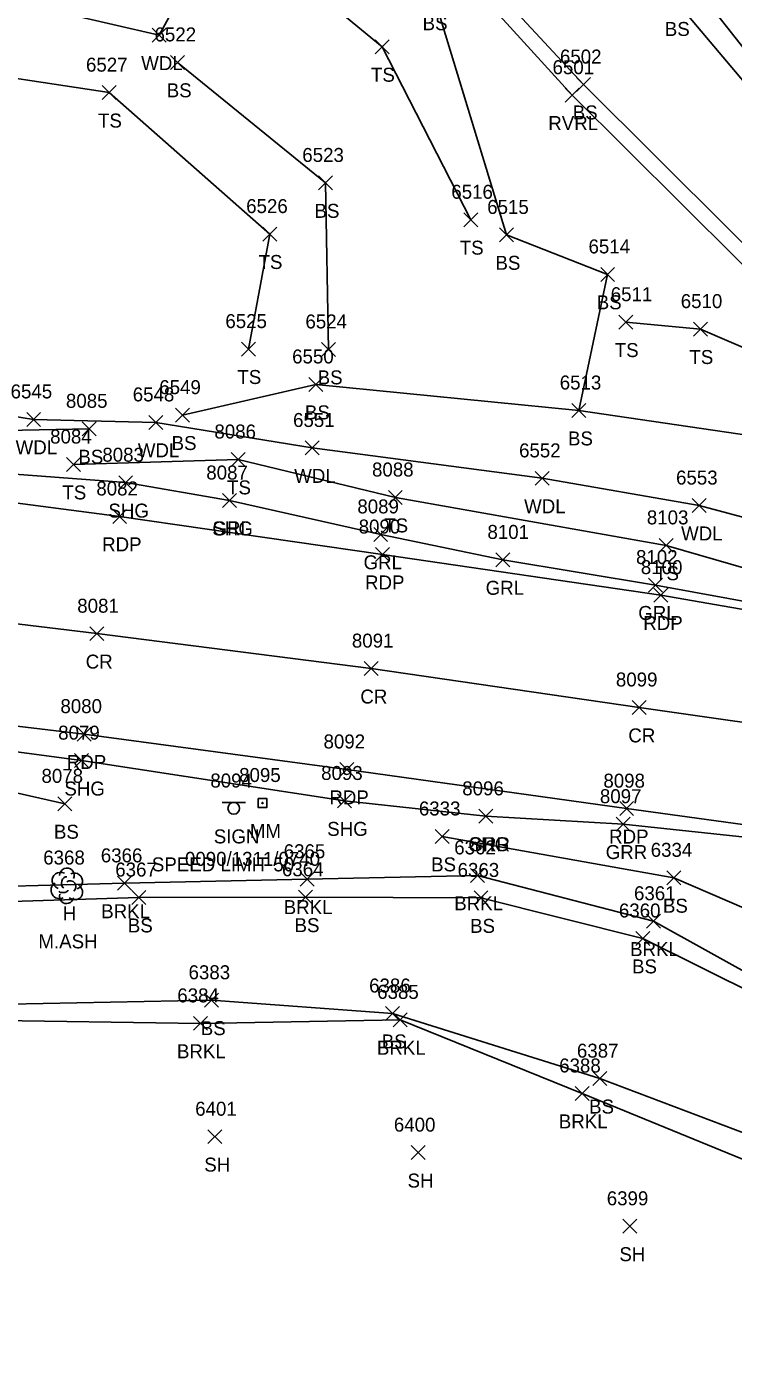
# Model space of a CAD drawing. Extents: x 1588028 to 1589597, y 137576 to 138176.
# Drawn here: x 1588774.4 to 1588875.5, y 137778.7 to 137969.2 of the extents above; entities that cross this region are included whole.
import ezdxf

# ---------------------------------------------------------------- set-up
doc = ezdxf.new("R2010")
doc.units = 0
for name, color, linetype in [('L_A', 7, 'Continuous'), ('L_C', 7, 'Continuous'), ('L_I', 7, 'Continuous'), ('L_TIC', 7, 'Continuous'), ('LAWA', 7, 'Continuous'), ('LAWE', 7, 'Continuous'), ('LELB', 7, 'Continuous'), ('LTD', 7, 'Continuous'), ('P_A', 7, 'Continuous'), ('P_I', 7, 'Continuous'), ('P_TIC', 7, 'Continuous'), ('PET', 7, 'Continuous'), ('PRC', 7, 'Continuous'), ('PSU', 7, 'Continuous'), ('R_A', 7, 'Continuous'), ('R_I', 7, 'Continuous'), ('R_TIC', 7, 'Continuous'), ('RGR', 7, 'Continuous'), ('S_A', 7, 'Continuous'), ('S_C', 7, 'Continuous'), ('S_I', 7, 'Continuous'), ('SRM', 7, 'Continuous'), ('SSGN', 7, 'Continuous')]:
    doc.layers.add(name, color=color, linetype=linetype)

msp = doc.modelspace()

# ---------------------------------------------------------------- linework, layer by layer
at = {"layer": 'L_TIC'}
for points in [[(1588792.35, 137966.95), (1588794.35, 137968.95)], [(1588794.35, 137966.95), (1588792.35, 137968.95)], [(1588824.25, 137965.29), (1588826.25, 137967.29)], [(1588826.25, 137965.29), (1588824.25, 137967.29)], [(1588794.99, 137963.06), (1588796.99, 137965.06)], [(1588796.99, 137963.06), (1588794.99, 137965.06)], [(1588853.1, 137959.89), (1588855.1, 137961.89)], [(1588855.1, 137959.89), (1588853.1, 137961.89)], [(1588785.18, 137958.73), (1588787.18, 137960.73)], [(1588787.18, 137958.73), (1588785.18, 137960.73)], [(1588851.47, 137958.37), (1588853.47, 137960.37)], [(1588853.47, 137958.37), (1588851.47, 137960.37)], [(1588816.14, 137945.81), (1588818.14, 137947.81)], [(1588818.14, 137945.81), (1588816.14, 137947.81)], [(1588836.96, 137940.54), (1588838.96, 137942.54)], [(1588838.96, 137940.54), (1588836.96, 137942.54)], [(1588808.17, 137938.49), (1588810.17, 137940.49)], [(1588810.17, 137938.49), (1588808.17, 137940.49)], [(1588842.04, 137938.37), (1588844.04, 137940.37)], [(1588844.04, 137938.37), (1588842.04, 137940.37)], [(1588856.54, 137932.72), (1588858.54, 137934.72)], [(1588858.54, 137932.72), (1588856.54, 137934.72)], [(1588859.16, 137925.88), (1588861.16, 137927.88)], [(1588861.16, 137925.88), (1588859.16, 137927.88)], [(1588869.83, 137924.89), (1588871.83, 137926.89)], [(1588871.83, 137924.89), (1588869.83, 137926.89)], [(1588805.13, 137922.03), (1588807.13, 137924.03)], [(1588807.13, 137922.03), (1588805.13, 137924.03)], [(1588816.59, 137921.98), (1588818.59, 137923.98)], [(1588818.59, 137921.98), (1588816.59, 137923.98)], [(1588814.77, 137916.97), (1588816.77, 137918.97)], [(1588816.77, 137916.97), (1588814.77, 137918.97)], [(1588852.42, 137913.24), (1588854.42, 137915.24)], [(1588854.42, 137913.24), (1588852.42, 137915.24)], [(1588774.38, 137911.97), (1588776.38, 137913.97)], [(1588776.38, 137911.97), (1588774.38, 137913.97)], [(1588791.87, 137911.54), (1588793.87, 137913.54)], [(1588793.87, 137911.54), (1588791.87, 137913.54)], [(1588795.68, 137912.58), (1588797.68, 137914.58)], [(1588797.68, 137912.58), (1588795.68, 137914.58)], [(1588782.34, 137910.62), (1588784.34, 137912.62)], [(1588784.34, 137910.62), (1588782.34, 137912.62)], [(1588814.25, 137907.88), (1588816.25, 137909.88)], [(1588816.25, 137907.88), (1588814.25, 137909.88)], [(1588780.08, 137905.51), (1588782.08, 137907.51)], [(1588782.08, 137905.51), (1588780.08, 137907.51)], [(1588803.65, 137906.23), (1588805.65, 137908.23)], [(1588805.65, 137906.23), (1588803.65, 137908.23)], [(1588847.17, 137903.53), (1588849.17, 137905.53)], [(1588849.17, 137903.53), (1588847.17, 137905.53)], [(1588826.15, 137900.79), (1588828.15, 137902.79)], [(1588828.15, 137900.79), (1588826.15, 137902.79)], [(1588869.64, 137899.64), (1588871.64, 137901.64)], [(1588871.64, 137899.64), (1588869.64, 137901.64)], [(1588864.92, 137893.94), (1588866.92, 137895.94)], [(1588866.92, 137893.94), (1588864.92, 137895.94)], [(1588778.84, 137856.95), (1588780.84, 137858.95)], [(1588780.84, 137856.95), (1588778.84, 137858.95)], [(1588832.83, 137852.28), (1588834.83, 137854.28)], [(1588834.83, 137852.28), (1588832.83, 137854.28)], [(1588837.93, 137846.71), (1588839.93, 137848.71)], [(1588839.93, 137846.71), (1588837.93, 137848.71)], [(1588787.4, 137845.57), (1588789.4, 137847.57)], [(1588789.4, 137845.57), (1588787.4, 137847.57)], [(1588813.53, 137846.16), (1588815.53, 137848.16)], [(1588815.53, 137846.16), (1588813.53, 137848.16)], [(1588866.01, 137846.36), (1588868.01, 137848.36)], [(1588868.01, 137846.36), (1588866.01, 137848.36)], [(1588789.42, 137843.54), (1588791.42, 137845.54)], [(1588791.42, 137843.54), (1588789.42, 137845.54)], [(1588813.28, 137843.58), (1588815.28, 137845.58)], [(1588815.28, 137843.58), (1588813.28, 137845.58)], [(1588838.41, 137843.48), (1588840.41, 137845.48)], [(1588840.41, 137843.48), (1588838.41, 137845.48)], [(1588863.1, 137840.15), (1588865.1, 137842.15)], [(1588865.1, 137840.15), (1588863.1, 137842.15)], [(1588861.59, 137837.68), (1588863.59, 137839.68)], [(1588863.59, 137837.68), (1588861.59, 137839.68)], [(1588799.85, 137828.84), (1588801.85, 137830.84)], [(1588801.85, 137828.84), (1588799.85, 137830.84)], [(1588798.24, 137825.53), (1588800.24, 137827.53)], [(1588800.24, 137825.53), (1588798.24, 137827.53)], [(1588825.76, 137826.94), (1588827.76, 137828.94)], [(1588827.76, 137826.94), (1588825.76, 137828.94)], [(1588826.86, 137826.03), (1588828.86, 137828.03)], [(1588828.86, 137826.03), (1588826.86, 137828.03)], [(1588855.44, 137817.62), (1588857.44, 137819.62)], [(1588857.44, 137817.62), (1588855.44, 137819.62)], [(1588852.9, 137815.5), (1588854.9, 137817.5)], [(1588854.9, 137815.5), (1588852.9, 137817.5)], [(1588800.32, 137809.31), (1588802.32, 137811.31)], [(1588802.32, 137809.31), (1588800.32, 137811.31)], [(1588829.41, 137807.03), (1588831.41, 137809.03)], [(1588831.41, 137807.03), (1588829.41, 137809.03)], [(1588859.73, 137796.49), (1588861.73, 137798.49)], [(1588861.73, 137796.49), (1588859.73, 137798.49)]]:
    msp.add_lwpolyline(points, dxfattribs=at)
at = {"layer": 'LAWA'}
for points in [[(1588762.05, 138028.09), (1588788.28, 138004.54), (1588803.93, 137987.32), (1588793.35, 137967.95), (1588766.76, 137974.1)], [(1588745.3, 137917.8), (1588775.38, 137912.97), (1588792.87, 137912.54), (1588815.25, 137908.88), (1588848.17, 137904.53), (1588870.64, 137900.64), (1588891.17, 137895.16)]]:
    msp.add_lwpolyline(points, dxfattribs=at)
at = {"layer": 'LAWE'}
for points in [[(1588434.56, 138062.89), (1588458.47, 138076.79), (1588495.54, 138110.89), (1588517.72, 138151.17), (1588540.38, 138168.38), (1588562.32, 138170.6), (1588586.16, 138148.71), (1588635.49, 138130.01), (1588676.05, 138127.99), (1588706.09, 138118.66), (1588727.82, 138096.85), (1588770.39, 138065.1), (1588798.8, 138043.18), (1588827.56, 138018.04), (1588869.93, 137975.12), (1588899.99, 137936.94), (1588912.08, 137921.5), (1588926.82, 137898.29), (1588932.86, 137884.09), (1588938.83, 137878.76)], [(1588441.02, 138044.54), (1588465.05, 138060.11), (1588492.43, 138083.39), (1588521.86, 138113.88), (1588530.72, 138143.54), (1588545.57, 138151.23), (1588554.85, 138142.99), (1588577.1, 138115.96), (1588614.25, 138110.98), (1588643.88, 138111.05), (1588664.41, 138106.89), (1588688.53, 138102.18), (1588718.75, 138082.48), (1588743.28, 138056.23), (1588764.53, 138038.44), (1588797.04, 138013.98), (1588814.47, 138001.04), (1588852.47, 137959.37), (1588883.95, 137928.09), (1588897.47, 137912.79), (1588913.44, 137894.45), (1588920.69, 137884.16), (1588921.99, 137878.45)], [(1588977.09, 137801.88), (1588949.99, 137800.55), (1588913.53, 137816.71), (1588888.44, 137827.65), (1588864.1, 137841.15), (1588838.93, 137847.71), (1588814.53, 137847.16), (1588788.4, 137846.57), (1588760.06, 137845.85), (1588744.31, 137852.31), (1588711.69, 137843.68)], [(1588713.41, 137823.71), (1588738.42, 137825.5), (1588767.27, 137826.98), (1588799.24, 137826.53), (1588827.86, 137827.03), (1588853.9, 137816.5), (1588892.67, 137800.6), (1588920.93, 137790.22), (1588953.81, 137785.34), (1588994.96, 137778.72)]]:
    msp.add_lwpolyline(points, dxfattribs=at)
at = {"layer": 'LELB'}
for points in [[(1588682.05, 138125.09), (1588705.48, 138117.82), (1588727.76, 138095.08), (1588769.43, 138063.36), (1588798.46, 138041.61), (1588826.19, 138016.5), (1588867.28, 137972.84), (1588898.61, 137935.76), (1588911.42, 137921.16), (1588925.66, 137898.09), (1588931.8, 137883.5), (1588937.54, 137876.95)], [(1588667.09, 138110.74), (1588688.84, 138110.6), (1588719.17, 138088.33), (1588744.4, 138063.38), (1588766.27, 138045.61), (1588798.27, 138018.43), (1588815.99, 138001.93), (1588854.1, 137960.89), (1588885.58, 137929.53), (1588899.45, 137912.94)], [(1588879.77, 137910.36), (1588853.42, 137914.24), (1588857.54, 137933.72), (1588843.04, 137939.37), (1588832.61, 137973.66), (1588809.98, 137996.61)], [(1588837.96, 137941.54), (1588825.25, 137966.29), (1588808.87, 137979.84)], [(1588806.13, 137923.03), (1588809.17, 137939.49), (1588786.18, 137959.73), (1588761.56, 137963.45), (1588758.19, 137959.11), (1588739.31, 137921.58)], [(1588795.99, 137964.06), (1588817.14, 137946.81), (1588817.59, 137922.98)], [(1588551.14, 137930.49), (1588555.16, 137922.7), (1588594.96, 137920.46), (1588624.61, 137918.77), (1588663.54, 137916.63), (1588704.8, 137915.23), (1588747.54, 137910.9), (1588783.34, 137911.62)], [(1588898.43, 137890.84), (1588893.87, 137897.04), (1588887.93, 137918.51), (1588870.83, 137925.89), (1588860.16, 137926.88)], [(1588796.68, 137913.58), (1588815.77, 137917.97)], [(1588815.77, 137917.97), (1588853.42, 137914.24)], [(1588781.08, 137906.51), (1588804.65, 137907.23), (1588827.15, 137901.79), (1588865.92, 137894.94), (1588900.81, 137884.83), (1588902.22, 137883.09)], [(1588723.44, 137868.13), (1588739.55, 137867.04), (1588779.84, 137857.95)], [(1588833.83, 137853.28), (1588867.01, 137847.36), (1588885.07, 137839.59), (1588900.79, 137841.16), (1588903.14, 137846.71), (1588926.9, 137843.7)], [(1588976.95, 137800.76), (1588950.62, 137796.9), (1588914.44, 137812.1), (1588887.83, 137826.14), (1588862.59, 137838.68), (1588839.41, 137844.48), (1588814.28, 137844.58), (1588790.42, 137844.54), (1588761.5, 137843.62), (1588744.06, 137845.91), (1588711.1, 137839.15), (1588710.72, 137829.12), (1588738.02, 137826.67), (1588767.07, 137829.2), (1588800.85, 137829.84), (1588826.76, 137827.94), (1588856.44, 137818.62), (1588893.47, 137804.61), (1588923.15, 137792.66), (1588953.98, 137786.08), (1588988.16, 137786.33)]]:
    msp.add_lwpolyline(points, dxfattribs=at)
at = {"layer": 'LTD'}
msp.add_line((1588780.11, 137846.26), (1588780.11, 137846.26), dxfattribs=at)
msp.add_line((1588780.11, 137846.26), (1588780.11, 137846.26), dxfattribs=at)
msp.add_arc((1588780.15, 137847.7), 1.05, 335.5272, 180.9563, dxfattribs=at)
for centre, major_axis, ratio, start_param, end_param in [((1588779.02, 137845.55), (0.58, -1.04), 0.959034, 3.141593, 6.283185), ((1588779.32, 137846.93), (1.21, -0.51), 0.895232, 1.570796, 4.712389), ((1588779.9, 137846.72), (-0.208, -0.792), 0.645439, 3.141593, 6.283185), ((1588780.61, 137846.1), (-0.5, 0.667), 0.989748, 3.141593, 6.283185), ((1588781.15, 137846.85), (-1.14, -0.48), 0.949671, 1.570796, 4.712389), ((1588780.11, 137844.76), (0.26, 1.06), 0.942809, 1.570796, 4.712389), ((1588779.65, 137845.51), (-0.625, -0.083), 0.423636, 0, 3.141593), ((1588781.11, 137845.43), (-1.09, 0.79), 0.841452, 1.570796, 4.712389)]:
    msp.add_ellipse(centre, major_axis=major_axis, ratio=ratio, start_param=start_param, end_param=end_param, dxfattribs=at)
at = {"layer": 'P_TIC'}
for points in [[(1588787.55, 137902.91), (1588789.55, 137904.91)], [(1588789.55, 137902.91), (1588787.55, 137904.91)], [(1588802.43, 137900.36), (1588804.43, 137902.36)], [(1588804.43, 137900.36), (1588802.43, 137902.36)], [(1588786.69, 137898.08), (1588788.69, 137900.08)], [(1588788.69, 137898.08), (1588786.69, 137900.08)], [(1588824.32, 137892.63), (1588826.32, 137894.63)], [(1588826.32, 137892.63), (1588824.32, 137894.63)], [(1588864.15, 137886.82), (1588866.15, 137888.82)], [(1588866.15, 137886.82), (1588864.15, 137888.82)], [(1588783.4, 137881.3), (1588785.4, 137883.3)], [(1588785.4, 137881.3), (1588783.4, 137883.3)], [(1588822.71, 137876.3), (1588824.71, 137878.3)], [(1588824.71, 137876.3), (1588822.71, 137878.3)], [(1588861.06, 137870.74), (1588863.06, 137872.74)], [(1588863.06, 137870.74), (1588861.06, 137872.74)], [(1588781.63, 137866.93), (1588783.63, 137868.93)], [(1588783.63, 137866.93), (1588781.63, 137868.93)], [(1588781.24, 137863.13), (1588783.24, 137865.13)], [(1588783.24, 137863.13), (1588781.24, 137865.13)], [(1588819.21, 137861.87), (1588821.21, 137863.87)], [(1588821.21, 137861.87), (1588819.21, 137863.87)], [(1588818.87, 137857.36), (1588820.87, 137859.36)], [(1588820.87, 137857.36), (1588818.87, 137859.36)], [(1588859.26, 137856.26), (1588861.26, 137858.26)], [(1588861.26, 137856.26), (1588859.26, 137858.26)], [(1588839.12, 137855.16), (1588841.12, 137857.16)], [(1588841.12, 137855.16), (1588839.12, 137857.16)]]:
    msp.add_lwpolyline(points, dxfattribs=at)
at = {"layer": 'PET'}
for points in [[(1588422.16, 137923.17), (1588469.2, 137920.73), (1588503.28, 137919.24), (1588517.55, 137918.56), (1588549.94, 137917.25), (1588592.35, 137915.11), (1588643.26, 137911.75), (1588663.5, 137910.85), (1588704.32, 137908.35), (1588747.19, 137904.38), (1588787.69, 137899.08), (1588825.32, 137893.63), (1588865.15, 137887.82), (1588905.82, 137880.77), (1588917.24, 137863.85), (1588927.99, 137847.51)], [(1588419.97, 137892.51), (1588466.09, 137889.91), (1588506.76, 137888.01), (1588548, 137885.78), (1588590.45, 137883.61), (1588638.45, 137880.69), (1588661.69, 137879.38), (1588677.51, 137878.09), (1588721.13, 137874.78), (1588740.19, 137872.99), (1588782.63, 137867.93), (1588820.21, 137862.87), (1588860.26, 137857.26), (1588914.01, 137849.9), (1588927.99, 137847.51)]]:
    msp.add_lwpolyline(points, dxfattribs=at)
at = {"layer": 'PRC'}
msp.add_lwpolyline([(1588420.99, 137907.2), (1588467.18, 137904.92), (1588507.29, 137903.21), (1588549.37, 137901.19), (1588590.55, 137899.3), (1588641.57, 137896.1), (1588661.53, 137894.88), (1588702.39, 137891.26), (1588744.44, 137887.15), (1588784.4, 137882.3), (1588823.71, 137877.3), (1588862.06, 137871.74), (1588917.24, 137863.85)], dxfattribs=at)
at = {"layer": 'PSU'}
for points in [[(1588548.35, 137920.32), (1588592.38, 137917.18), (1588643.62, 137914.8), (1588663.46, 137913.57), (1588704.41, 137911.28), (1588747.22, 137907.04), (1588788.55, 137903.91), (1588803.43, 137901.36)], [(1588721.03, 137871.04), (1588739.68, 137869.83), (1588782.24, 137864.13), (1588819.87, 137858.36), (1588840.12, 137856.16)]]:
    msp.add_lwpolyline(points, dxfattribs=at)
at = {"layer": 'R_TIC'}
for points in [[(1588802.43, 137900.36), (1588804.43, 137902.36)], [(1588804.43, 137900.36), (1588802.43, 137902.36)], [(1588824.05, 137895.51), (1588826.05, 137897.51)], [(1588826.05, 137895.51), (1588824.05, 137897.51)], [(1588841.53, 137891.86), (1588843.53, 137893.86)], [(1588843.53, 137891.86), (1588841.53, 137893.86)], [(1588863.38, 137888.26), (1588865.38, 137890.26)], [(1588865.38, 137888.26), (1588863.38, 137890.26)], [(1588839.12, 137855.16), (1588841.12, 137857.16)], [(1588841.12, 137855.16), (1588839.12, 137857.16)], [(1588858.77, 137854.04), (1588860.77, 137856.04)], [(1588860.77, 137854.04), (1588858.77, 137856.04)]]:
    msp.add_lwpolyline(points, dxfattribs=at)
at = {"layer": 'RGR'}
for points in [[(1588803.43, 137901.36), (1588825.05, 137896.51), (1588842.53, 137892.86), (1588864.38, 137889.26), (1588901.77, 137882.43)], [(1588840.12, 137856.16), (1588859.77, 137855.04), (1588913.91, 137849.25), (1588926.96, 137847)]]:
    msp.add_lwpolyline(points, dxfattribs=at)
at = {"layer": 'SRM'}
msp.add_lwpolyline([(1588807.51, 137858.69), (1588808.76, 137858.69), (1588808.76, 137857.44), (1588807.51, 137857.44)], close=True, dxfattribs=at)
msp.add_circle((1588808.13, 137858.07), 0.0833, dxfattribs=at)
at = {"layer": 'SSGN'}
for p, q in [((1588802.38, 137858.13), (1588805.71, 137858.13)), ((1588804.02, 137857.3), (1588804.02, 137857.3))]:
    msp.add_line(p, q, dxfattribs=at)
msp.add_circle((1588804.02, 137857.3), 0.833, dxfattribs=at)

# ---------------------------------------------------------------- texts
at = {"layer": 'L_A'}
for s, p in [('BS', (1588831.05, 137968.66)), ('BS', (1588865.72, 137967.84)), ('WDL', (1588790.77, 137962.95)), ('TS', (1588823.66, 137961.29)), ('BS', (1588794.43, 137959.06)), ('BS', (1588852.54, 137955.89)), ('TS', (1588784.59, 137954.73)), ('RVRL', (1588849.04, 137954.37)), ('BS', (1588815.58, 137941.81)), ('TS', (1588836.37, 137936.54)), ('TS', (1588807.57, 137934.49)), ('BS', (1588841.48, 137934.37)), ('BS', (1588855.98, 137928.72)), ('TS', (1588858.56, 137921.88)), ('TS', (1588869.24, 137920.89)), ('TS', (1588804.54, 137918.03)), ('BS', (1588816.03, 137917.98)), ('BS', (1588814.21, 137912.97)), ('WDL', (1588772.8, 137907.97)), ('WDL', (1588790.29, 137907.54)), ('BS', (1588795.12, 137908.58)), ('BS', (1588851.86, 137909.24)), ('BS', (1588781.78, 137906.62)), ('WDL', (1588812.67, 137903.88)), ('TS', (1588803.06, 137902.23)), ('TS', (1588779.49, 137901.51)), ('WDL', (1588845.58, 137899.53)), ('TS', (1588825.56, 137896.79)), ('WDL', (1588868.05, 137895.64)), ('TS', (1588864.33, 137889.94)), ('BS', (1588778.28, 137852.95)), ('BS', (1588832.27, 137848.28)), ('BRKL', (1588835.58, 137842.71)), ('H', (1588779.54, 137841.26)), ('BRKL', (1588785.05, 137841.57)), ('BRKL', (1588811.17, 137842.16)), ('BS', (1588865.45, 137842.36)), ('BS', (1588788.86, 137839.54)), ('BS', (1588812.72, 137839.58)), ('BS', (1588837.85, 137839.48)), ('BRKL', (1588860.75, 137836.15)), ('BS', (1588861.03, 137833.68)), ('BS', (1588799.3, 137824.84)), ('BRKL', (1588824.51, 137822.03)), ('BS', (1588825.2, 137822.94)), ('BRKL', (1588795.89, 137821.53)), ('BS', (1588854.88, 137813.62)), ('BRKL', (1588850.55, 137811.5)), ('SH', (1588799.8, 137805.31)), ('SH', (1588828.9, 137803.03)), ('SH', (1588859.22, 137792.49))]:
    msp.add_text(s, height=2, dxfattribs=at).set_placement(p)
at = {"layer": 'L_C'}
msp.add_text('M.ASH', height=2, dxfattribs=at).set_placement((1588776.06, 137837.26))
at = {"layer": 'L_I'}
for s, p in [('6522', (1588792.68, 137967.06)), ('6527', (1588782.87, 137962.73)), ('6502', (1588850.71, 137963.89)), ('6501', (1588849.65, 137962.37)), ('6523', (1588813.83, 137949.81)), ('6516', (1588835.16, 137944.54)), ('6526', (1588805.8, 137942.49)), ('6515', (1588840.3, 137942.37)), ('6514', (1588854.8, 137936.72)), ('6511', (1588857.98, 137929.88)), ('6510', (1588868, 137928.89)), ('6525', (1588802.82, 137926.03)), ('6524', (1588814.28, 137925.98)), ('6550', (1588812.38, 137920.97)), ('6513', (1588850.68, 137917.24)), ('6545', (1588772.08, 137915.97)), ('6548', (1588789.56, 137915.54)), ('6549', (1588793.36, 137916.58)), ('8085', (1588780, 137914.62)), ('6551', (1588812.51, 137911.88)), ('8084', (1588777.74, 137909.51)), ('8086', (1588801.25, 137910.23)), ('6552', (1588844.86, 137907.53)), ('8088', (1588823.81, 137904.79)), ('6553', (1588867.33, 137903.64)), ('8103', (1588863.15, 137897.94)), ('8078', (1588776.5, 137860.95)), ('6333', (1588830.52, 137856.28)), ('6362', (1588835.58, 137850.71)), ('6334', (1588863.7, 137850.36)), ('6368', (1588776.75, 137849.26)), ('6366', (1588784.99, 137849.57)), ('6365', (1588811.17, 137850.16)), ('6367', (1588787.06, 137847.54)), ('6364', (1588810.92, 137847.58)), ('6363', (1588836.06, 137847.48)), ('6361', (1588861.31, 137844.15)), ('6360', (1588859.15, 137841.68)), ('6383', (1588797.55, 137832.84)), ('6384', (1588795.94, 137829.53)), ('6386', (1588823.4, 137830.94)), ('6385', (1588824.55, 137830.03)), ('6387', (1588853.14, 137821.62)), ('6388', (1588850.6, 137819.5)), ('6401', (1588798.5, 137813.31)), ('6400', (1588826.94, 137811.03)), ('6399', (1588857.41, 137800.49))]:
    msp.add_text(s, height=2, dxfattribs=at).set_placement(p)
at = {"layer": 'P_A'}
for s, p in [('SHG', (1588786.08, 137898.91)), ('SHG', (1588800.96, 137896.36)), ('RDP', (1588785.18, 137894.08)), ('RDP', (1588822.81, 137888.63)), ('RDP', (1588862.64, 137882.82)), ('CR', (1588782.83, 137877.3)), ('CR', (1588822.14, 137872.3)), ('CR', (1588860.5, 137866.74)), ('RDP', (1588780.12, 137862.93)), ('SHG', (1588779.78, 137859.13)), ('RDP', (1588817.7, 137857.87)), ('SHG', (1588817.4, 137853.36)), ('RDP', (1588857.75, 137852.26)), ('SHG', (1588837.66, 137851.16))]:
    msp.add_text(s, height=2, dxfattribs=at).set_placement(p)
at = {"layer": 'P_I'}
for s, p in [('8083', (1588785.21, 137906.91)), ('8087', (1588800.09, 137904.36)), ('8082', (1588784.35, 137902.08)), ('8090', (1588821.9, 137896.63)), ('8100', (1588862.29, 137890.82)), ('8081', (1588781.62, 137885.3)), ('8091', (1588820.93, 137880.3)), ('8099', (1588858.72, 137874.74)), ('8080', (1588779.21, 137870.93)), ('8079', (1588778.89, 137867.13)), ('8092', (1588816.87, 137865.87)), ('8093', (1588816.53, 137861.36)), ('8098', (1588856.93, 137860.26)), ('8096', (1588836.73, 137859.16))]:
    msp.add_text(s, height=2, dxfattribs=at).set_placement(p)
at = {"layer": 'R_A'}
for s, p in [('GRL', (1588800.97, 137896.36)), ('GRL', (1588822.6, 137891.51)), ('GRL', (1588840.08, 137887.86)), ('GRL', (1588861.92, 137884.26)), ('GRR', (1588837.61, 137851.16)), ('GRR', (1588857.26, 137850.04))]:
    msp.add_text(s, height=2, dxfattribs=at).set_placement(p)
at = {"layer": 'R_I'}
for s, p in [('8087', (1588800.09, 137904.36)), ('8089', (1588821.71, 137899.51)), ('8101', (1588840.33, 137895.86)), ('8102', (1588861.6, 137892.26)), ('8096', (1588836.73, 137859.16)), ('8097', (1588856.43, 137858.04))]:
    msp.add_text(s, height=2, dxfattribs=at).set_placement(p)
at = {"layer": 'S_A'}
for s, p in [('SIGN', (1588801.16, 137852.28)), ('MM', (1588806.32, 137853.07))]:
    msp.add_text(s, height=2, dxfattribs=at).set_placement(p)
at = {"layer": 'S_C'}
for s, p in [('0090/1311/0740', (1588797.04, 137849.07)), ('SPEED LIMIT 50', (1588792.3, 137848.28))]:
    msp.add_text(s, height=2, dxfattribs=at).set_placement(p)
at = {"layer": 'S_I'}
for s, p in [('8094', (1588800.67, 137860.28)), ('8095', (1588804.79, 137861.07))]:
    msp.add_text(s, height=2, dxfattribs=at).set_placement(p)

doc.saveas('drawing.dxf')
